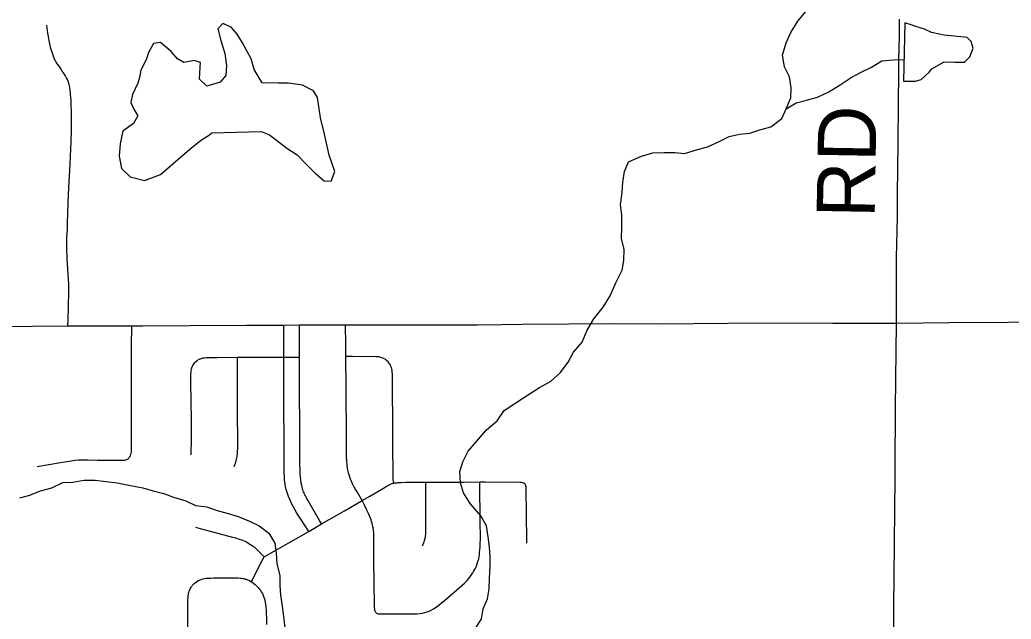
# Model space of a CAD drawing. Extents: x 0 to 34, y 0 to 22.
# Drawn here: x 6.128 to 7.097, y 16.163 to 16.749 of the extents above; entities that cross this region are included whole.
import ezdxf

# ---------------------------------------------------------------- set-up
doc = ezdxf.new("R2010")
doc.units = 0
for name, color, linetype in [('GM_X_County_Road', 7, 'Continuous'), ('GM_X_County_Road_Text', 7, 'Continuous'), ('GM_X_Minor_Lake', 7, 'Continuous'), ('GM_X_Minor_River', 7, 'Continuous'), ('GM_X_Township_Road', 7, 'Continuous')]:
    doc.layers.add(name, color=color, linetype=linetype)

msp = doc.modelspace()

# ---------------------------------------------------------------- linework, layer by layer
at = {"layer": 'GM_X_County_Road'}
for points in [[(6.98487, 16.45265), (6.98499, 16.48409), (6.98512, 16.51639), (6.98523, 16.53007), (6.98561, 16.54247), (6.98586, 16.55736), (6.98593, 16.57911), (6.98661, 16.62819), (6.98703, 16.66795), (6.98723, 16.69653), (6.98733, 16.70896), (6.98784, 16.73378), (6.98799, 16.74993)], [(6.98237, 16.12529), (6.98252, 16.17571), (6.98276, 16.20558), (6.98318, 16.23599), (6.98332, 16.27144), (6.98353, 16.2994), (6.9837, 16.31868), (6.98383, 16.33111), (6.98396, 16.35034), (6.984, 16.35904), (6.98408, 16.36711), (6.98409, 16.37207), (6.98413, 16.37578), (6.98416, 16.37824), (6.98424, 16.38826), (6.98434, 16.39762), (6.98487, 16.45265)]]:
    msp.add_lwpolyline(points, dxfattribs=at)
at = {"layer": 'GM_X_Minor_Lake'}
for p, q in [((6.99317, 16.74617), (6.99173, 16.68929)), ((6.3158, 16.63862), (6.36385, 16.64013))]:
    msp.add_line(p, q, dxfattribs=at)
for points in [[(6.36385, 16.64013), (6.3722, 16.63678), (6.37906, 16.63152), (6.38896, 16.62364), (6.39923, 16.61727), (6.40686, 16.60899), (6.41678, 16.59921), (6.42555, 16.59169), (6.43236, 16.59136), (6.43607, 16.60087), (6.43027, 16.61675), (6.42594, 16.63757), (6.42203, 16.65347), (6.41885, 16.67316), (6.41501, 16.67995), (6.40437, 16.68518), (6.39072, 16.68735), (6.38051, 16.68727), (6.36499, 16.68754), (6.35694, 16.70074), (6.3542, 16.71096), (6.34575, 16.72682), (6.34039, 16.73512), (6.33466, 16.7419), (6.3263, 16.74563), (6.32142, 16.74029), (6.32454, 16.72893), (6.32843, 16.71645), (6.33003, 16.70471), (6.32935, 16.69485), (6.32373, 16.68836), (6.31089, 16.68447), (6.30365, 16.69124), (6.30431, 16.703), (6.30465, 16.70755), (6.29858, 16.7094), (6.28838, 16.70742), (6.28229, 16.71117), (6.2758, 16.71832), (6.26552, 16.72697), (6.25871, 16.72616), (6.25386, 16.7174), (6.25165, 16.71018), (6.24643, 16.6999), (6.24497, 16.69268), (6.2435, 16.68736), (6.23829, 16.67633), (6.23646, 16.66835), (6.23954, 16.66193), (6.24337, 16.65551), (6.23927, 16.6479), (6.22873, 16.64023), (6.22618, 16.62808), (6.22514, 16.61594), (6.22751, 16.60382), (6.2359, 16.59554), (6.24993, 16.59224), (6.2654, 16.59805), (6.28232, 16.61258), (6.29435, 16.62291), (6.3045, 16.63133), (6.31354, 16.63671), (6.3158, 16.63862)], [(6.99173, 16.68929), (7.00346, 16.68938), (7.00912, 16.69094), (7.01701, 16.6982), (7.01964, 16.70125), (7.0317, 16.70817), (7.04192, 16.70787), (7.05138, 16.70794), (7.05664, 16.71291), (7.05997, 16.72166), (7.05803, 16.72809), (7.05422, 16.73185), (7.04475, 16.73292), (7.03149, 16.73433), (7.01936, 16.7369), (7.01252, 16.74025), (7.00379, 16.74284), (6.99924, 16.74432), (6.99317, 16.74617)]]:
    msp.add_lwpolyline(points, dxfattribs=at)
at = {"layer": 'GM_X_Minor_River'}
for points in [[(6.57286, 16.15301), (6.57921, 16.16329), (6.58102, 16.17317), (6.58511, 16.18305), (6.58692, 16.19292), (6.58722, 16.20316), (6.58788, 16.21454), (6.58781, 16.22402), (6.58698, 16.23349), (6.58576, 16.24372), (6.58416, 16.25432), (6.57879, 16.26414), (6.56809, 16.27619), (6.56157, 16.28675), (6.55884, 16.29659), (6.558, 16.30758), (6.56095, 16.31708), (6.56617, 16.32736), (6.57442, 16.3369), (6.58417, 16.34835), (6.5947, 16.35715), (6.60143, 16.36706), (6.62327, 16.38163), (6.63607, 16.38969), (6.64662, 16.39546), (6.65639, 16.40426), (6.66388, 16.41455), (6.6691, 16.42407), (6.67773, 16.43399), (6.68255, 16.44578), (6.68928, 16.45683), (6.69827, 16.46827), (6.705, 16.47932), (6.71057, 16.49188), (6.71691, 16.50443), (6.71835, 16.51393), (6.71864, 16.52492), (6.71629, 16.53514), (6.71657, 16.54652), (6.71648, 16.55827), (6.71526, 16.5685), (6.71669, 16.58026), (6.71736, 16.59051), (6.71917, 16.60076), (6.72288, 16.61026), (6.7357, 16.61605), (6.74665, 16.61917), (6.75762, 16.61963), (6.76822, 16.61933), (6.77807, 16.61865), (6.78826, 16.62176), (6.80035, 16.62488), (6.81091, 16.6299), (6.82146, 16.63528), (6.83167, 16.63726), (6.8415, 16.63847), (6.85131, 16.64158), (6.86226, 16.6447), (6.8728, 16.65274), (6.87726, 16.66225), (6.88172, 16.6729), (6.88202, 16.68276), (6.88042, 16.69337), (6.87543, 16.70319), (6.87344, 16.71455), (6.87713, 16.72671), (6.88159, 16.73698), (6.8887, 16.74803), (6.89657, 16.75757)], [(6.87726, 16.66225), (6.88706, 16.66801), (6.89688, 16.67074), (6.90783, 16.67348), (6.91876, 16.67887), (6.93006, 16.68578), (6.94061, 16.69269), (6.9504, 16.69807), (6.96058, 16.70308), (6.97075, 16.70922), (6.9821, 16.71007), (6.99227, 16.71057)], [(6.12788, 16.28191), (6.1377, 16.28426), (6.14826, 16.28851), (6.15921, 16.29163), (6.17015, 16.29665), (6.17999, 16.2971), (6.19057, 16.29908), (6.20154, 16.29916), (6.21253, 16.29773), (6.22314, 16.29629), (6.23451, 16.29411), (6.24815, 16.29156), (6.2584, 16.2886), (6.26864, 16.28603), (6.27813, 16.28231), (6.29026, 16.27899), (6.29977, 16.27413), (6.31075, 16.27308), (6.321, 16.26937), (6.33162, 16.26642), (6.34148, 16.26346), (6.3525, 16.25899), (6.36199, 16.25451), (6.37151, 16.24738), (6.37727, 16.23757), (6.37848, 16.22772), (6.37932, 16.21711), (6.38206, 16.20576), (6.38214, 16.19628), (6.38297, 16.18643), (6.38457, 16.17583), (6.38579, 16.1656), (6.38701, 16.15461)]]:
    msp.add_lwpolyline(points, dxfattribs=at)
at = {"layer": 'GM_X_Township_Road'}
for points in [[(6.17499, 16.44989), (6.17515, 16.45549), (6.17594, 16.48278), (6.17594, 16.48722), (6.17587, 16.49087), (6.17567, 16.49566), (6.17445, 16.51546), (6.17422, 16.51921), (6.17403, 16.52342), (6.17397, 16.52583), (6.17392, 16.52908), (6.17393, 16.5315), (6.17398, 16.53342), (6.1741, 16.53631), (6.17449, 16.54465), (6.17472, 16.55106), (6.17493, 16.55955), (6.17535, 16.57064), (6.17591, 16.58533), (6.17729, 16.60822), (6.17769, 16.61596), (6.178, 16.62294), (6.17823, 16.62965), (6.17844, 16.64225), (6.17845, 16.65532), (6.17841, 16.65886), (6.17827, 16.66598), (6.1782, 16.66762), (6.17812, 16.66957), (6.17805, 16.67109), (6.1779, 16.6735), (6.17767, 16.67662), (6.17754, 16.67806), (6.17737, 16.67961), (6.17725, 16.68057), (6.17694, 16.68268), (6.1766, 16.68462), (6.17625, 16.68612), (6.17591, 16.68722), (6.17556, 16.68825), (6.17515, 16.68934), (6.17455, 16.69076), (6.17371, 16.6924), (6.17256, 16.6944), (6.17136, 16.69635), (6.16911, 16.69971), (6.16766, 16.70185), (6.16633, 16.70378), (6.16514, 16.70554), (6.16419, 16.70695), (6.16324, 16.70847), (6.16292, 16.70904), (6.16243, 16.70995), (6.16199, 16.71085), (6.16158, 16.71181), (6.16102, 16.71325), (6.16014, 16.71572), (6.1584, 16.7211), (6.15759, 16.72415), (6.15655, 16.72912), (6.15593, 16.73286), (6.15543, 16.73633), (6.15454, 16.74414)], [(6.98487, 16.45265), (7.03686, 16.45323), (7.09462, 16.45343), (7.14938, 16.45381), (7.22263, 16.45456), (7.2871, 16.45457), (7.30348, 16.45458), (7.35809, 16.45465), (7.38729, 16.45513), (7.40778, 16.45529), (7.42885, 16.4554), (7.52745, 16.4559), (7.57328, 16.45572), (7.68181, 16.45668), (7.72164, 16.45714), (7.77194, 16.45847), (7.79161, 16.45861), (7.80491, 16.45879), (7.82731, 16.45876)], [(5.98503, 16.44897), (6.01572, 16.44897), (6.08218, 16.44904), (6.0977, 16.44913), (6.11694, 16.44924), (6.14047, 16.4496), (6.17499, 16.44989)], [(6.17499, 16.44989), (6.19447, 16.45005), (6.22367, 16.44998), (6.23744, 16.44986)], [(6.23418, 16.32028), (6.23487, 16.32097), (6.23535, 16.32156), (6.23613, 16.32293), (6.23655, 16.32401), (6.23694, 16.32561), (6.23708, 16.3267), (6.23716, 16.32807), (6.23718, 16.33134), (6.23725, 16.34002), (6.23717, 16.37537), (6.23704, 16.39862), (6.23721, 16.42793), (6.23721, 16.43285), (6.2374, 16.44703), (6.23744, 16.44986)], [(6.23744, 16.44986), (6.24814, 16.44994), (6.2935, 16.45015), (6.34917, 16.45056), (6.38599, 16.45073)], [(6.38599, 16.45073), (6.40142, 16.45087), (6.44632, 16.4511)], [(6.41041, 16.249), (6.40814, 16.25253), (6.40146, 16.26293), (6.39955, 16.26594), (6.39863, 16.26744), (6.39691, 16.27033), (6.39531, 16.27316), (6.39405, 16.27557), (6.39218, 16.27953), (6.39066, 16.28301), (6.38964, 16.28593), (6.38928, 16.2871), (6.38874, 16.28903), (6.3885, 16.28997), (6.3878, 16.29291), (6.38739, 16.29511), (6.38707, 16.29751), (6.38688, 16.2991), (6.38677, 16.30036), (6.3866, 16.30285), (6.38649, 16.30511), (6.3864, 16.30781), (6.38631, 16.31208), (6.38633, 16.32895), (6.38624, 16.38036), (6.38606, 16.41938), (6.386, 16.44662), (6.38599, 16.45073)], [(6.42299, 16.25626), (6.42098, 16.25973), (6.40947, 16.27964), (6.40865, 16.28108), (6.40799, 16.28228), (6.40725, 16.28376), (6.40674, 16.28478), (6.40641, 16.28545), (6.40592, 16.28652), (6.40544, 16.28758), (6.40513, 16.28838), (6.40472, 16.28954), (6.40443, 16.29046), (6.4039, 16.29247), (6.40316, 16.29617), (6.40269, 16.29935), (6.40239, 16.30203), (6.40214, 16.30585), (6.40187, 16.31802), (6.40153, 16.4194), (6.40144, 16.44795), (6.40142, 16.45087)], [(6.44632, 16.4511), (6.46091, 16.45106), (6.48888, 16.45105), (6.5268, 16.45102), (6.54234, 16.45094), (6.55843, 16.45082), (6.57496, 16.45102), (6.59915, 16.45138), (6.61903, 16.45158), (6.70997, 16.45222), (6.75255, 16.45202), (6.81995, 16.45256), (6.84855, 16.45278), (6.92267, 16.45248), (6.97907, 16.45255), (6.98487, 16.45265)], [(6.47598, 16.16956), (6.47557, 16.17018), (6.47522, 16.1709), (6.47503, 16.17166), (6.47492, 16.17248), (6.47488, 16.17313), (6.47486, 16.17391), (6.47432, 16.2018), (6.47422, 16.21737), (6.47416, 16.22919), (6.47419, 16.23706), (6.47417, 16.24132), (6.47412, 16.24393), (6.47398, 16.24712), (6.47368, 16.25012), (6.47332, 16.25256), (6.47312, 16.25356), (6.4727, 16.25546), (6.47238, 16.25677), (6.47189, 16.25855), (6.47137, 16.26029), (6.47082, 16.26184), (6.46997, 16.26405), (6.46896, 16.26635), (6.46734, 16.26987), (6.46495, 16.27472), (6.46259, 16.27913), (6.45765, 16.28754), (6.45596, 16.29047), (6.45466, 16.29277), (6.45326, 16.29551), (6.45247, 16.29718), (6.45182, 16.29875), (6.45128, 16.30006), (6.45061, 16.30195), (6.44989, 16.30411), (6.44937, 16.30585), (6.44891, 16.30789), (6.44842, 16.31031), (6.44823, 16.3115), (6.448, 16.31315), (6.44786, 16.31437), (6.44765, 16.31724), (6.44744, 16.3229), (6.44736, 16.32636), (6.44736, 16.34286), (6.44723, 16.36202), (6.44711, 16.36752), (6.44705, 16.38291), (6.44705, 16.38909), (6.44679, 16.41997), (6.44666, 16.43568), (6.44642, 16.44672), (6.44632, 16.4511)], [(6.29545, 16.32367), (6.29549, 16.32554), (6.29577, 16.33795), (6.29597, 16.34855), (6.29567, 16.36101), (6.29552, 16.37275), (6.29516, 16.39823), (6.29518, 16.39941), (6.29522, 16.40175), (6.29527, 16.40306), (6.29536, 16.40459), (6.2956, 16.4065), (6.2959, 16.40798), (6.29644, 16.40975), (6.29718, 16.4113), (6.29769, 16.41216), (6.29832, 16.4131), (6.29906, 16.41401), (6.30014, 16.41512), (6.30133, 16.41604), (6.30207, 16.41656), (6.30273, 16.41697), (6.30396, 16.41759), (6.30459, 16.41784), (6.30543, 16.41813), (6.30611, 16.41833), (6.30686, 16.41852), (6.30767, 16.41868), (6.3084, 16.41881), (6.31019, 16.419), (6.31145, 16.41908), (6.313, 16.41912), (6.31439, 16.41912), (6.32079, 16.41903), (6.34067, 16.41923), (6.35142, 16.41935), (6.3769, 16.41939), (6.38606, 16.41938), (6.38923, 16.41938), (6.40153, 16.4194)], [(6.33761, 16.31252), (6.33818, 16.31396), (6.33868, 16.31535), (6.33896, 16.3162), (6.33937, 16.31762), (6.33961, 16.31853), (6.3398, 16.31938), (6.34009, 16.32074), (6.34034, 16.32211), (6.34047, 16.32308), (6.34065, 16.32469), (6.34073, 16.32551), (6.34083, 16.32665), (6.34104, 16.33024), (6.34114, 16.3337), (6.3409, 16.36809), (6.3408, 16.38323), (6.34067, 16.41636), (6.34067, 16.41923)], [(6.49367, 16.2961), (6.49342, 16.29759), (6.49311, 16.29954), (6.49295, 16.30183), (6.49255, 16.33554), (6.4925, 16.36345), (6.49236, 16.37951), (6.49238, 16.39589), (6.49229, 16.40274), (6.49214, 16.40489), (6.49201, 16.40622), (6.49166, 16.408), (6.49125, 16.40938), (6.49051, 16.41119), (6.48998, 16.41219), (6.48889, 16.41377), (6.48795, 16.41479), (6.48651, 16.41613), (6.48576, 16.41672), (6.48504, 16.41723), (6.48354, 16.41812), (6.48227, 16.41872), (6.48132, 16.41908), (6.47983, 16.41945), (6.47902, 16.4196), (6.47811, 16.41971), (6.47744, 16.41976), (6.47611, 16.41981), (6.45317, 16.41994), (6.44679, 16.41997)], [(6.20393, 16.3187), (6.22088, 16.31853), (6.22829, 16.31856), (6.22912, 16.31859), (6.23032, 16.3187), (6.23169, 16.319), (6.23248, 16.31929), (6.23311, 16.3196), (6.23418, 16.32028)], [(6.14503, 16.31251), (6.16775, 16.31624), (6.17822, 16.31805), (6.18204, 16.31852), (6.18549, 16.31878), (6.18962, 16.31893), (6.19496, 16.31895), (6.20393, 16.3187)], [(6.35444, 16.19974), (6.3633, 16.21761), (6.36688, 16.22416), (6.38113, 16.23211), (6.41041, 16.249), (6.42299, 16.25626), (6.44537, 16.26917), (6.46259, 16.27913), (6.4701, 16.28347), (6.48185, 16.29041), (6.48778, 16.2939), (6.4898, 16.29492), (6.4911, 16.29544), (6.49305, 16.29599), (6.49367, 16.2961), (6.49472, 16.29631), (6.49689, 16.29659), (6.49769, 16.29665), (6.50048, 16.29679), (6.50547, 16.29696), (6.52496, 16.29707), (6.52723, 16.29708), (6.54464, 16.29719), (6.56203, 16.29725), (6.57768, 16.29738), (6.58315, 16.29743), (6.61687, 16.29718), (6.61819, 16.29703), (6.61924, 16.29681), (6.62021, 16.29646), (6.62116, 16.29589)], [(6.47598, 16.16956), (6.47657, 16.16896), (6.47721, 16.1686), (6.47819, 16.16839), (6.47902, 16.16832), (6.47975, 16.16829), (6.48065, 16.16827), (6.48295, 16.16826), (6.49563, 16.16823), (6.51307, 16.16826), (6.51597, 16.16839), (6.5192, 16.16863), (6.5217, 16.16898), (6.52406, 16.16949), (6.52613, 16.17014), (6.52802, 16.17086), (6.53013, 16.17185), (6.5325, 16.17322), (6.53494, 16.17483), (6.53805, 16.17712), (6.54037, 16.17902), (6.54294, 16.1812), (6.56002, 16.19597), (6.56262, 16.19841), (6.56517, 16.20098), (6.56648, 16.20248), (6.56782, 16.20411), (6.5686, 16.2051), (6.56927, 16.20602), (6.56999, 16.20709), (6.57082, 16.20835), (6.57161, 16.2096), (6.57228, 16.21073), (6.57318, 16.21248), (6.57396, 16.21423), (6.57464, 16.21588), (6.57522, 16.2176), (6.5762, 16.22062), (6.57656, 16.22217), (6.57693, 16.22395), (6.57726, 16.22587), (6.57752, 16.22818), (6.57778, 16.23103), (6.57797, 16.23397), (6.57814, 16.23766), (6.57822, 16.24096), (6.57797, 16.26066), (6.57771, 16.29367), (6.57768, 16.29738)], [(6.52165, 16.23476), (6.52321, 16.23885), (6.52368, 16.24017), (6.52392, 16.24092), (6.52423, 16.24203), (6.5244, 16.24278), (6.52454, 16.24357), (6.52466, 16.24448), (6.52477, 16.24582), (6.52483, 16.24705), (6.52487, 16.24858), (6.52488, 16.24929), (6.5249, 16.25092), (6.52484, 16.27626), (6.52495, 16.29443), (6.52496, 16.29707)], [(6.62368, 16.23753), (6.62364, 16.24001), (6.62292, 16.29084), (6.62286, 16.29246), (6.62272, 16.29347), (6.62245, 16.29433), (6.62203, 16.29502), (6.62116, 16.29589)], [(6.2998, 16.25294), (6.30423, 16.25187), (6.33596, 16.24345), (6.339, 16.24258), (6.34256, 16.24147), (6.34496, 16.24059), (6.34782, 16.23937), (6.34995, 16.2383), (6.3536, 16.23624), (6.35513, 16.23522), (6.35707, 16.23378), (6.35869, 16.23234), (6.36688, 16.22416)], [(6.29235, 16.11073), (6.29227, 16.16485), (6.29228, 16.17966), (6.29235, 16.18241), (6.29243, 16.18379), (6.29249, 16.18498), (6.29265, 16.1863), (6.29286, 16.18764), (6.29321, 16.18925), (6.29362, 16.19059), (6.29411, 16.19189), (6.29493, 16.19358), (6.29541, 16.19437), (6.29592, 16.19512), (6.29633, 16.19571), (6.29693, 16.19646), (6.29749, 16.19711), (6.29833, 16.19793), (6.29927, 16.19875), (6.30056, 16.19971), (6.30198, 16.20054), (6.30425, 16.20164), (6.30603, 16.20232), (6.30729, 16.20271), (6.30852, 16.20295), (6.31021, 16.20318), (6.3115, 16.2033), (6.31334, 16.20337), (6.31458, 16.20337), (6.31755, 16.20341), (6.32487, 16.20353), (6.33322, 16.20351), (6.33839, 16.20347), (6.34128, 16.20338), (6.34343, 16.20325), (6.34454, 16.20313), (6.34579, 16.20297), (6.34681, 16.20277), (6.34753, 16.20259), (6.34836, 16.20236), (6.34922, 16.20211), (6.34987, 16.2019), (6.35049, 16.20168), (6.3519, 16.20111), (6.35298, 16.2006), (6.35444, 16.19974)], [(6.35444, 16.19974), (6.35527, 16.19919), (6.35687, 16.19796), (6.35806, 16.19695), (6.35913, 16.19599), (6.36023, 16.19488), (6.36089, 16.19415), (6.36176, 16.19314), (6.36223, 16.19255), (6.36315, 16.1913), (6.36403, 16.18995), (6.36496, 16.18839), (6.3654, 16.18751), (6.3659, 16.18639), (6.36627, 16.18544), (6.36663, 16.18451), (6.36697, 16.18352), (6.36742, 16.18194), (6.36762, 16.1811), (6.36794, 16.17952), (6.3682, 16.178), (6.3683, 16.17729), (6.36844, 16.17605), (6.36855, 16.17475), (6.36875, 16.17157), (6.3689, 16.16809), (6.36899, 16.1648), (6.36912, 16.15797)]]:
    msp.add_lwpolyline(points, dxfattribs=at)

# ---------------------------------------------------------------- texts
at = {"layer": 'GM_X_County_Road_Text'}
msp.add_text('RD', height=0.056818, rotation=89.01384, dxfattribs=at).set_placement((6.96362, 16.55516))

doc.saveas('drawing.dxf')
